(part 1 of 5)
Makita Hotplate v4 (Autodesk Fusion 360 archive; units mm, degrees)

design "Makita Hotplate" references "Hotplate Toolchanger", "Makita RT0700 v10"
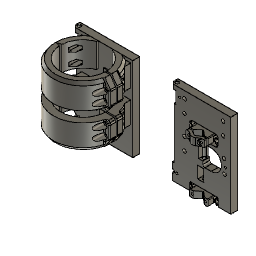
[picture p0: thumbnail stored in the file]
external_derived "ExternalDerived1"
split "Split1" bodies "Hotplate Cam Template (1)"
external_derived "ExternalDerived2"
move "Move1"
move "Move2"
move "Move3"
move "Move4"
work_plane "WorkPlane1"
work_plane "WorkPlane2" AlongDistance -29
sketch "Sketch1" plane through (7.3531, -5.0045, 68.3543) normal (0, 0, -1) x axis (1, 0, 0)
  line L1 (0, 1.1219) -> (0, 0)
  line L2 (-2.2027, 1.1219) -> (0, 1.1219)
  curve K1 (-2.2027, 1.1219) -> (-1.8409, 0.1808)
  line L3 (0, 1.1219) -> (0, 0)
  line L4 (4.5, 1.1219) -> (4.5, 0)
  line L5 (0.8469, -0.0045) -> (-5.1531, -0.0045)
  line L6 (0.8469, -0.0045) -> (3.6753, -0.0045)
  line L7 (12.6469, -0.0045) -> (3.6753, -0.0045)
  line L8 (12.6469, -0.0045) -> (27.1469, -0.0045)
  line L9 (3.6753, -0.0045) -> (12.6469, -0.0045)
  line L10 (3.6753, -0.0045) -> (0.8469, -0.0045)
  line L11 (-5.1531, -0.0045) -> (0.8469, -0.0045)
  line L12 (31.4969, -0.0045) -> (34.7969, -0.0045)
  line L13 (-34.0031, -0.0045) -> (-30.7031, -0.0045)
  line L14 (-38.0031, -0.0045) -> (-34.7031, -0.0045)
  line L15 (1.8969, -0.0045) -> (-6.6031, -0.0045)
  line L16 (-6.6031, -0.0045) -> (1.8969, -0.0045)
  line L17 (37.6469, -0.0045) -> (-42.8531, -0.0045)
  line L18 (-41.7031, -0.0045) -> (37.6469, -0.0045)
  line L19 (-37.7031, -0.0045) -> (-41.7031, -0.0045)
  line L20 (-35.3531, -0.0045) -> (-37.7031, -0.0045)
  line L21 (-34.8531, -0.0045) -> (-35.3531, -0.0045)
  line L22 (-35.3531, -0.0045) -> (-34.8531, -0.0045)
  line L23 (-42.8531, -0.0045) -> (-35.3531, -0.0045)
  line L24 (-38.9531, -0.0045) -> (-42.8531, -0.0045)
  line L25 (-42.8531, -0.0045) -> (-38.9531, -0.0045)
  line L26 (4.5, 1.1219) -> (0, 1.1219)
  line L27 (0, 0) -> (0, 1.1219)
  line L28 (4.5, 1.1219) -> (0, 1.1219)
  line L29 (4.5, 0) -> (4.5, 1.1219)
  line L30 (0, 0) -> (4.5, 0)
  line L31 (0, 1.1219) -> (0, 0)
  arc A1 centre (2.25, 32.3719) radius 32.45 clockwise from (0, 0) to (-1.8409, 0.1808)
  point P5 (0, 1.1219)
  point P31 (0, 1.1219)
  point P10 (4.5, 1.1219)
  point P32 (4.5, 1.1219)
  point P8 (0, 1.1219)
  point P33 (0, 1.1219)
  point P3 (0, 0)
  point P34 (0, 0)
  point P9 (4.5, 0)
  point P36 (4.5, 0)
  coincident P5 P31
  coincident P10 P32
  coincident P8 P33
  coincident P3 P34
  horizontal L28
  vertical L29
  horizontal L30
  vertical L31
  coincident P9 P36
extrude "Extrude1" new body sketch "Sketch1" profile of L1 L3 L4 L26 L27 L28 L29 L30 L31 to an object
extrude "Extrude2" add of existing geometry blind 5.5
sketch "Sketch2" plane through (0, -5, 0) normal (0, -1, 0) x axis (1, 0, 0)
  line L1 (8.2, 63) -> (2.2, 63)
  line L2 (8.2, 65.1716) -> (8.2, 63)
  curve K1 (8.2, 65.1716) -> (11.0284, 68)
  line L3 (20, 68) -> (11.0284, 68)
  line L4 (11.0284, 39) -> (20, 39)
  curve K2 (11.0284, 39) -> (8.2, 41.8284)
  line L5 (8.2, 46) -> (8.2, 41.8284)
  line L6 (2.2, 46) -> (8.2, 46)
  line L7 (2.2, 63) -> (2.2, 46)
  line L8 (9.25, 37) -> (0.75, 37)
  line L9 (9.25, 20) -> (9.25, 37)
  line L10 (0.75, 20) -> (9.25, 20)
  line L11 (0.75, 37) -> (0.75, 20)
  line L12 (-35.5, 0) -> (-35.5, 8.6225)
  line L13 (45, 0) -> (-35.5, 0)
  line L14 (45, 120) -> (45, 0)
  line L15 (-34.35, 120) -> (45, 120)
  line L16 (-34.35, 114) -> (-34.35, 120)
  line L17 (-30.35, 114) -> (-34.35, 114)
  line L18 (-30.35, 96.75) -> (-30.35, 114)
  line L19 (-28, 96.75) -> (-30.35, 96.75)
  line L20 (-28, 73.95) -> (-28, 96.75)
  line L21 (-27.5, 73.95) -> (-28, 73.95)
  line L22 (-27.5, 46.05) -> (-27.5, 73.95)
  line L23 (-28, 46.05) -> (-27.5, 46.05)
  line L24 (-28, 23.25) -> (-28, 46.05)
  line L25 (-35.5, 23.25) -> (-28, 23.25)
  line L26 (-35.5, 15.3775) -> (-35.5, 23.25)
  line L27 (-31.6, 12) -> (-35.5, 15.3775)
  line L28 (-35.5, 8.6225) -> (-31.6, 12)
  arc A1 centre (20, 53.5) radius 14.5 clockwise from (20, 68) to (20, 39)
  circle C1 centre (40.5, 54) radius 1.65
  circle C2 centre (-25, 108) radius 1.65
  circle C3 centre (-29, 12) radius 1.65
sketch "Sketch3" plane through (0, -6.1264, 0) normal (0, -1, 0) x axis (1, 0, 0)
  line L1 (7.3531, 91.3543) -> (11.8531, 91.3543)
  line L2 (7.3531, 62.8543) -> (7.3531, 91.3543)
  line L3 (11.8531, 62.8543) -> (7.3531, 62.8543)
  line L4 (11.8531, 91.3543) -> (11.8531, 62.8543)
  line L5 (8.2, 63) -> (2.2, 63)
  line L6 (8.2, 65.1716) -> (8.2, 63)
  curve K1 (8.2, 65.1716) -> (11.0284, 68)
  line L7 (20, 68) -> (11.0284, 68)
  line L8 (11.0284, 39) -> (20, 39)
  curve K2 (11.0284, 39) -> (8.2, 41.8284)
  line L9 (8.2, 46) -> (8.2, 41.8284)
  line L10 (2.2, 46) -> (8.2, 46)
  line L11 (2.2, 63) -> (2.2, 46)
  line L12 (9.25, 37) -> (0.75, 37)
  line L13 (9.25, 20) -> (9.25, 37)
  line L14 (0.75, 20) -> (9.25, 20)
  line L15 (0.75, 37) -> (0.75, 20)
  line L16 (-35.5, 0) -> (-35.5, 8.6225)
  line L17 (45, 0) -> (-35.5, 0)
  line L18 (45, 120) -> (45, 0)
  line L19 (-34.35, 120) -> (45, 120)
  line L20 (-34.35, 114) -> (-34.35, 120)
  line L21 (-30.35, 114) -> (-34.35, 114)
  line L22 (-30.35, 96.75) -> (-30.35, 114)
  line L23 (-28, 96.75) -> (-30.35, 96.75)
  line L24 (-28, 73.95) -> (-28, 96.75)
  line L25 (-27.5, 73.95) -> (-28, 73.95)
  line L26 (-27.5, 46.05) -> (-27.5, 73.95)
  line L27 (-28, 46.05) -> (-27.5, 46.05)
  line L28 (-28, 23.25) -> (-28, 46.05)
  line L29 (-35.5, 23.25) -> (-28, 23.25)
  line L30 (-35.5, 15.3775) -> (-35.5, 23.25)
  line L31 (-31.6, 12) -> (-35.5, 15.3775)
  line L32 (-35.5, 8.6225) -> (-31.6, 12)
  arc A1 centre (20, 53.5) radius 14.5 clockwise from (20, 68) to (20, 39)
  circle C1 centre (40.5, 54) radius 1.65
  circle C2 centre (-25, 108) radius 1.65
  circle C3 centre (-29, 12) radius 1.65
extrude "Extrude3" new body blind 6 second side blind 3
split "Split2"
combine "Combine1" bodies "Hotplate Cam Template"
combine "Combine2"
extrude "Extrude4" add of existing geometry blind -5
sketch "Sketch4" plane through (-28, 0, 0) normal (-1, 0, 0) x axis (0, -1, 0)
  line L1 (5, 96.75) -> (5, 73.95)
  line L2 (-0.7, 96.75) -> (5, 96.75)
  line L3 (-0.7, 73.95) -> (-0.7, 96.75)
  line L4 (5, 73.95) -> (-0.7, 73.95)
  line L5 (-5, 98.4571) -> (-5, 97.25)
  line L6 (-5, 114) -> (-5, 98.4571)
  line L7 (-5, 120) -> (-5, 114)
  line L8 (-5, 0) -> (-5, 120)
  line L9 (-5, 22.25) -> (-5, 0)
  line L10 (-5, 22.75) -> (-5, 22.25)
  line L11 (-5, 97.25) -> (-5, 22.75)
  line L12 (-5, 37) -> (-5, 20)
  line L13 (-5, 20) -> (-5, 37)
  line L14 (-5, 10.35) -> (-5, 13.65)
  line L15 (-5, 106.35) -> (-5, 109.65)
  line L16 (-5, 52.35) -> (-5, 55.65)
  line L17 (-5, 63) -> (-5, 65.1716)
  line L18 (-5, 46) -> (-5, 63)
  line L19 (-5, 41.8284) -> (-5, 46)
  line L20 (-5, 41.8284) -> (-5, 39)
  line L21 (-5, 39) -> (-5, 68)
  line L22 (-5, 68) -> (-5, 65.1716)
  line L23 (-5, 96.75) -> (5, 96.75)
  line L24 (-5, 22.75) -> (-5, 96.75)
  line L25 (5, 22.75) -> (-5, 22.75)
  line L26 (5, 96.75) -> (5, 22.75)
  circle C1 centre (3, 92.5) radius 1.75
  circle C2 centre (3, 76.45) radius 0.85
  point P15 (-5, 22.75)
  point P32 (-5, 22.75)
  point P8 (5, 96.75)
  point P30 (5, 96.75)
  horizontal L23
  vertical L24
  horizontal L25
  vertical L26
  coincident P15 P32
  coincident P8 P30
extrude "Extrude5" add sketch "Sketch4" profile of C1 C2 L1 L2 L3 L4 L8 L11 L12 L13 L16 L17 L18 L19 L20 L21 L22 L23 L24 L25 L26 along normal blind 5 and against normal blind 10
sketch "Sketch5" plane through (0, 0, 120) normal (0, 0, 1) x axis (-1, 0, 0)
  line L1 (34.35, 5) -> (37.35, 2)
  line L2 (-45, 5) -> (34.35, 5)
  line L3 (-45, -5) -> (-45, 5)
  line L4 (37.35, -5) -> (-45, -5)
  line L5 (37.35, 2) -> (37.35, -5)
  line L6 (-11.8531, 5) -> (-7.3531, 5)
  line L7 (-20, 5) -> (-11.8531, 5)
  line L8 (-34.5, 5) -> (-20, 5)
  line L9 (-11.0284, 5) -> (-20, 5)
  line L10 (-11.0284, 5) -> (-8.2, 5)
  line L11 (-2.2, 5) -> (-8.2, 5)
  line L12 (-7.3531, 5) -> (-2.2, 5)
  line L13 (-42.15, 5) -> (-38.85, 5)
  line L14 (23.35, 5) -> (26.65, 5)
  line L15 (27.35, 5) -> (30.65, 5)
  line L16 (-9.25, 5) -> (-0.75, 5)
  line L17 (-0.75, 5) -> (-9.25, 5)
  line L18 (33, 5) -> (30.35, 5)
  line L19 (35.5, 5) -> (33, 5)
  line L20 (31.6, 5) -> (35.5, 5)
  line L21 (35.5, 5) -> (31.6, 5)
  line L22 (-45, 5) -> (35.5, 5)
  line L23 (34.35, 5) -> (-45, 5)
  line L24 (30.35, 5) -> (34.35, 5)
  circle C1 centre (33.35, 0) radius 2.625
  arc A1 centre (-9.6031, 37.3764) radius 32.45 clockwise from (22.7653, 39.6764) to (22.7653, 35.0764)
  arc A2 centre (-9.6031, 37.3764) radius 32.45 clockwise from (22.7653, 39.6764) to (22.8469, 37.3764)
  arc A3 centre (-9.6031, 37.3764) radius 32.45 clockwise from (-13.694, 5.1853) to (22.8469, 37.3764)
  arc A4 centre (-9.6031, 37.3764) radius 32.45 clockwise from (-11.8531, 5.0045) to (-13.694, 5.1853)
  arc A5 centre (-9.6031, 37.3764) radius 32.45 clockwise from (-7.3531, 5.0045) to (-11.8531, 5.0045)
  arc A6 centre (-9.6031, 37.3764) radius 32.45 clockwise from (-5.5122, 5.1853) to (-7.3531, 5.0045)
  arc A7 centre (-9.6031, 37.3764) radius 32.45 clockwise from (22.8469, 37.3764) to (-5.5122, 5.1853)
  arc A8 centre (-9.6031, 37.3764) radius 32.45 clockwise from (22.8469, 37.3764) to (22.7653, 35.0764)
  arc A9 centre (-9.6031, 37.3764) radius 32.45 clockwise from (22.7653, 39.6764) to (22.7653, 35.0764)
  arc A10 centre (-9.6031, 37.3764) radius 32.45 clockwise from (22.7653, 39.6764) to (22.7653, 35.0764)
  arc A11 centre (-9.6031, 37.3764) radius 32.45 clockwise from (22.7653, 39.6764) to (22.7653, 35.0764)
  arc A12 centre (-9.6031, 37.3764) radius 32.45 clockwise from (22.7653, 39.6764) to (22.7653, 35.0764)
  arc A13 centre (-9.6031, 37.3764) radius 32.45 clockwise from (22.7653, 39.6764) to (22.7653, 35.0764)
  arc A14 centre (-9.6031, 37.3764) radius 32.45 clockwise from (22.7653, 39.6764) to (22.7653, 35.0764)
  arc A15 centre (-9.6031, 37.3764) radius 32.45 clockwise from (22.7653, 39.6764) to (22.7653, 35.0764)
  arc A16 centre (-9.6031, 37.3764) radius 32.45 clockwise from (22.7653, 39.6764) to (22.7653, 35.0764)
  arc A17 centre (-9.6031, 37.3764) radius 32.45 clockwise from (22.7653, 39.6764) to (22.7653, 35.0764)
  arc A18 centre (-9.6031, 37.3764) radius 32.45 clockwise from (22.7653, 39.6764) to (22.7653, 35.0764)
  arc A19 centre (-9.6031, 37.3764) radius 32.45 clockwise from (22.7653, 39.6764) to (22.7653, 35.0764)
  arc A20 centre (-9.6031, 37.3764) radius 32.45 clockwise from (22.7653, 39.6764) to (22.7653, 35.0764)
  arc A21 centre (-9.6031, 37.3764) radius 32.45 clockwise from (22.7653, 39.6764) to (22.7653, 35.0764)
  arc A22 centre (-9.6031, 37.3764) radius 32.45 clockwise from (22.7653, 39.6764) to (22.7653, 35.0764)
  arc A23 centre (-9.6031, 37.3764) radius 32.45 clockwise from (22.7653, 39.6764) to (22.7653, 35.0764)
  arc A24 centre (-9.6031, 37.3764) radius 32.45 clockwise from (22.7653, 39.6764) to (22.7653, 35.0764)
  arc A25 centre (-9.6031, 37.3764) radius 32.45 clockwise from (22.7653, 39.6764) to (22.7653, 35.0764)
  arc A26 centre (-9.6031, 37.3764) radius 32.45 clockwise from (22.7653, 39.6764) to (22.7653, 35.0764)
  arc A27 centre (-9.6031, 37.3764) radius 32.45 clockwise from (22.7653, 39.6764) to (22.7653, 35.0764)
  arc A28 centre (-9.6031, 37.3764) radius 32.45 clockwise from (22.7653, 39.6764) to (22.7653, 35.0764)
  arc A29 centre (-9.6031, 37.3764) radius 32.45 clockwise from (22.7653, 39.6764) to (22.7653, 35.0764)
  arc A30 centre (-9.6031, 37.3764) radius 32.45 clockwise from (22.7653, 39.6764) to (22.7653, 35.0764)
  arc A31 centre (-9.6031, 37.3764) radius 32.45 clockwise from (22.7653, 39.6764) to (22.7653, 35.0764)
  arc A32 centre (-9.6031, 37.3764) radius 32.45 clockwise from (22.7653, 39.6764) to (22.7653, 35.0764)
  arc A33 centre (-9.6031, 37.3764) radius 32.45 clockwise from (22.7653, 39.6764) to (22.7653, 35.0764)
  arc A34 centre (-9.6031, 37.3764) radius 32.45 clockwise from (22.7653, 39.6764) to (22.7653, 35.0764)
  arc A35 centre (-9.6031, 37.3764) radius 32.45 clockwise from (22.7653, 39.6764) to (22.7653, 35.0764)
  arc A36 centre (-9.6031, 37.3764) radius 32.45 clockwise from (22.7653, 39.6764) to (22.7653, 35.0764)
  arc A37 centre (-9.6031, 37.3764) radius 32.45 clockwise from (22.7653, 39.6764) to (22.7653, 35.0764)
  arc A38 centre (-9.6031, 37.3764) radius 32.45 clockwise from (22.7653, 39.6764) to (22.7653, 35.0764)
  arc A39 centre (-9.6031, 37.3764) radius 32.45 clockwise from (22.7653, 39.6764) to (22.7653, 35.0764)
  arc A40 centre (-9.6031, 37.3764) radius 32.45 clockwise from (22.7653, 39.6764) to (22.7653, 35.0764)
  arc A41 centre (-9.6031, 37.3764) radius 32.45 clockwise from (22.7653, 39.6764) to (22.7653, 35.0764)
  arc A42 centre (-9.6031, 37.3764) radius 32.45 clockwise from (22.7653, 39.6764) to (22.7653, 35.0764)
  arc A43 centre (-9.6031, 37.3764) radius 32.45 clockwise from (22.7653, 39.6764) to (22.7653, 35.0764)
  arc A44 centre (-9.6031, 37.3764) radius 32.45 clockwise from (22.7653, 39.6764) to (22.7653, 35.0764)
  arc A45 centre (-9.6031, 37.3764) radius 32.45 clockwise from (22.7653, 39.6764) to (22.7653, 35.0764)
  arc A46 centre (-9.6031, 37.3764) radius 32.45 clockwise from (22.7653, 39.6764) to (22.7653, 35.0764)
  arc A47 centre (-9.6031, 37.3764) radius 32.45 clockwise from (22.7653, 39.6764) to (22.7653, 35.0764)
  arc A48 centre (-9.6031, 37.3764) radius 32.45 clockwise from (22.7653, 39.6764) to (22.7653, 35.0764)
  arc A49 centre (-9.6031, 37.3764) radius 32.45 clockwise from (22.7653, 39.6764) to (22.7653, 35.0764)
  arc A50 centre (-9.6031, 37.3764) radius 32.45 clockwise from (22.7653, 39.6764) to (22.7653, 35.0764)
  arc A51 centre (-9.6031, 37.3764) radius 32.45 clockwise from (22.7653, 39.6764) to (22.7653, 35.0764)
  arc A52 centre (-9.6031, 37.3764) radius 32.45 clockwise from (22.7653, 39.6764) to (22.7653, 35.0764)
  circle C2 centre (-9.6031, 37.3764) radius 32.45
  arc A53 centre (-9.6031, 37.3764) radius 32.45 clockwise from (22.7653, 39.6764) to (22.7653, 35.0764)
  arc A54 centre (-9.6031, 37.3764) radius 32.45 clockwise from (22.7653, 39.6764) to (22.7653, 35.0764)
  circle C3 centre (-9.6031, 37.3764) radius 42.45
  dimension "d16" = 10
extrude "Extrude6" new body sketch "Sketch5" profile of L2 A1 A2 A3 A4 A5 A6 A7 A8 A9 A10 A11 A12 A13 A14 A15 A16 A17 A18 A19 A20 A21 A22 A23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 against normal blind 35
copy_paste_bodies "CopyPasteBodies1"
move "Move5"
extrude "Extrude7" cut sketch "Sketch2" profile of L1 L2 K1 L3 A1 L4 K2 L5 L6 L7 along normal blind 15
chamfer "Chamfer1" distance 3 Rotate Angle 55 bodies "Body1 (1)"
combine "Combine3"
sketch "Sketch6" plane through (45, 0, 0) normal (1, 0, 0) x axis (0, 1, 0)
  line L1 (5, 120) -> (5, 0)
  line L2 (-5, 120) -> (5, 120)
  line L3 (-5, 0) -> (-5, 120)
  line L4 (5, 0) -> (-5, 0)
  line L5 (-79.8264, 115.7156) -> (-5, 115.7156)
  line L6 (-5, 85) -> (-79.8264, 85)
  line L7 (-79.8264, 70) -> (-5, 70)
  line L8 (-5, 39.2844) -> (-79.8264, 39.2844)
  line L9 (-14.1517, 115.7156) -> (-5, 115.7156)
  line L10 (-14.1517, 85) -> (-14.1517, 115.7156)
  line L11 (-5, 85) -> (-14.1517, 85)
  line L12 (-5, 115.7156) -> (-5, 85)
  line L13 (-14.4254, 70) -> (-5, 70)
  line L14 (-14.4254, 39.2844) -> (-14.4254, 70)
  line L15 (-5, 39.2844) -> (-14.4254, 39.2844)
  line L16 (-5, 70) -> (-5, 39.2844)
  point P16 (-14.1517, 85)
  point P6 (-5, 115.7156)
  point P14 (-5, 115.7156)
  point P20 (-14.4254, 39.2844)
  point P10 (-5, 70)
  point P18 (-5, 70)
  horizontal L9
  vertical L10
  horizontal L11
  vertical L12
  coincident L6 P16
  coincident P6 P14
  horizontal L13
  vertical L14
  horizontal L15
  vertical L16
  coincident L8 P20
  coincident P10 P18
extrude "Extrude8" new body sketch "Sketch6" profile of L3 L5 L6 L7 L8 L9 L10 L11 L12 L13 L14 L15 L16 against normal blind 70
split "Split3"
combine "Combine4"
split "Split4"
sketch "Sketch7" plane through (0, -5, 0) normal (0, 1, 0) x axis (-1, 0, 0)
  line L1 (-0.75, 37) -> (-0.75, 35)
  line L2 (-7.4192, 37) -> (-0.75, 37)
  line L3 (-7.4192, 35) -> (-7.4192, 37)
  line L4 (-0.75, 35) -> (-7.4192, 35)
extrude "Extrude9" cut sketch "Sketch7" against normal blind 12
sketch "Sketch8" plane through (0, 0, 70) normal (0, 0, 1) x axis (-1, 0, 0)
  line L1 (-11.8531, 5) -> (-37.058, 5)
  line L2 (-11.8531, 5.0045) -> (-11.8531, 5)
  line L3 (-7.3531, 5) -> (-7.3531, 5.0045)
  line L4 (25, 5) -> (-7.3531, 5)
  line L5 (25, 12.7873) -> (25, 5)
  line L6 (-45, 5) -> (-45, -5)
  line L7 (-45, 13.9443) -> (-45, 5)
  line L8 (-45, 5) -> (-45, 13.9443)
  line L9 (-45, -5) -> (-45, 5)
  line L10 (-45, 5) -> (-37.058, 5)
  arc A1 centre (-9.6031, 37.3764) radius 42.45 clockwise from (-37.058, 5) to (25, 12.7873)
  arc A2 centre (-9.6031, 37.3764) radius 32.45 clockwise from (-11.8531, 5.0045) to (-7.3531, 5.0045)
  arc A3 centre (-9.6031, 37.3764) radius 42.45 clockwise from (-37.058, 5) to (25, 12.7873)
  point P14 (-37.058, 5)
  point P16 (-37.058, 5)
  point P11 (-45, 5)
  point P17 (-45, 5)
  coincident P14 P16
  coincident P11 P17
extrude "Extrude10" add sketch "Sketch8" profile of A1 L7 L8 A3 L10 against normal blind 30.716
sketch "Sketch9" plane through (0, 0, 120) normal (0, 0, 1) x axis (-1, 0, 0)
  line L1 (-45, 5) -> (-32.1435, 5)
  line L2 (-45, -5) -> (-45, 5)
  line L3 (37.35, -5) -> (-45, -5)
  line L4 (37.35, 2) -> (37.35, -5)
  line L5 (34.35, 5) -> (37.35, 2)
  line L6 (12.9373, 5) -> (34.35, 5)
  line L7 (-11.787, 5) -> (-7.4192, 5)
  arc A1 centre (-9.6031, 37.3764) radius 39.45 clockwise from (-32.1435, 5) to (12.9373, 5)
  circle C1 centre (33.35, 0) radius 2.625
  arc A2 centre (-9.6031, 37.3764) radius 32.45 clockwise from (-11.787, 5) to (-7.4192, 5)
  arc A3 centre (-9.6031, 37.3764) radius 32.45 clockwise from (-11.787, 5) to (-7.4192, 5)
sketch "Sketch10" plane through (0, 0, 120) normal (0, 0, 1) x axis (-1, 0, 0)
  line L1 (-45, 5) -> (-32.1435, 5)
  line L2 (-45, -5) -> (-45, 5)
  line L3 (37.35, -5) -> (-45, -5)
  line L4 (37.35, 2) -> (37.35, -5)
  line L5 (34.35, 5) -> (37.35, 2)
  line L6 (12.9373, 5) -> (34.35, 5)
  line L7 (-11.787, 5) -> (-7.4192, 5)
  line L8 (-68.9773, 5) -> (34.35, 5)
  line L9 (-68.9773, 90.7472) -> (-68.9773, 5)
  line L10 (34.35, 90.7472) -> (-68.9773, 90.7472)
  line L11 (34.35, 5) -> (34.35, 90.7472)
  arc A1 centre (-9.6031, 37.3764) radius 39.45 clockwise from (-32.1435, 5) to (12.9373, 5)
  circle C1 centre (33.35, 0) radius 2.625
  arc A2 centre (-9.6031, 37.3764) radius 32.45 clockwise from (-11.787, 5) to (-7.4192, 5)
  point P9 (34.35, 5)
  point P15 (34.35, 5)
  horizontal L8
  vertical L9
  horizontal L10
  vertical L11
  coincident P9 P15
extrude "Extrude11" new body sketch "Sketch10" profile of A1 L1 L6 L7 A2 L8 L9 L10 L11 against normal blind 145
split "Split5"
sketch "Sketch11" plane through (0, -5, 0) normal (0, -1, 0) x axis (1, 0, 0)
  line L1 (11.0284, 39) -> (20, 39)
  curve K1 (11.0284, 39) -> (8.2, 41.8284)
  line L2 (8.2, 46) -> (8.2, 41.8284)
  line L3 (2.2, 46) -> (8.2, 46)
  line L4 (2.2, 63) -> (2.2, 46)
  line L5 (8.2, 63) -> (2.2, 63)
  line L6 (8.2, 65.1716) -> (8.2, 63)
  curve K2 (8.2, 65.1716) -> (11.0284, 68)
  line L7 (20, 68) -> (11.0284, 68)
  line L8 (9.25, 37) -> (0.75, 37)
  line L9 (9.25, 20) -> (9.25, 37)
  line L10 (0.75, 20) -> (9.25, 20)
  line L11 (0.75, 37) -> (0.75, 20)
  line L12 (-35.5, 8.6225) -> (-31.6, 12)
  line L13 (-35.5, 0) -> (-35.5, 8.6225)
  line L14 (45, 0) -> (-35.5, 0)
  line L15 (45, 120) -> (45, 0)
  line L16 (-34.35, 120) -> (45, 120)
  line L17 (-34.35, 114) -> (-34.35, 120)
  line L18 (-30.35, 114) -> (-34.35, 114)
  line L19 (-30.35, 96.75) -> (-30.35, 114)
  line L20 (-33, 96.75) -> (-30.35, 96.75)
  line L21 (-33, 23.25) -> (-33, 96.75)
  line L22 (-35.5, 23.25) -> (-33, 23.25)
  line L23 (-35.5, 15.3775) -> (-35.5, 23.25)
  line L24 (-31.6, 12) -> (-35.5, 15.3775)
  line L25 (11.8531, 68) -> (11.0284, 68)
  line L26 (11.8531, 91.3543) -> (11.8531, 68)
  line L27 (7.3531, 91.3543) -> (11.8531, 91.3543)
  line L28 (7.3531, 63) -> (7.3531, 91.3543)
  line L29 (8.2, 63) -> (7.3531, 63)
  line L30 (8.2, 65.1716) -> (8.2, 63)
  curve K3 (11.0284, 68) -> (8.2, 65.1716)
  arc A1 centre (20, 53.5) radius 14.5 clockwise from (20, 68) to (20, 39)
  circle C1 centre (-25, 108) radius 1.65
  circle C2 centre (40.5, 54) radius 1.65
  circle C3 centre (-29, 12) radius 1.65
extrude "Extrude12" add sketch "Sketch11" profile of L5 L6 K2 L7 L25 L26 L27 L28 L29 L30 K3 along normal blind 1.122
extrude "Extrude13" cut of existing geometry blind -39
sketch "Sketch12" plane through (0, 0, 120) normal (0, 0, 1) x axis (-1, 0, 0)
  line L1 (-11.787, 5) -> (-32.1435, 5)
  line L2 (12.9373, 5) -> (-7.4192, 5)
  line L3 (29.1901, 37.3764) -> (-9.6031, 37.3764)
  line L4 (28.4052, 37.1373) -> (22.7882, 35.4258)
  line L5 (28.4052, 37.6156) -> (22.7882, 39.3271)
  arc A1 centre (-9.6031, 37.3764) radius 32.45 clockwise from (-11.787, 5) to (-7.4192, 5)
  arc A2 centre (-9.6031, 37.3764) radius 39.45 clockwise from (-32.1435, 5) to (12.9373, 5)
  arc A3 centre (-9.6031, 37.3764) radius 32.45 clockwise from (-11.787, 5) to (-7.4192, 5)
  arc A4 centre (28.3324, 37.3764) radius 0.25 clockwise from (28.4052, 37.6156) to (28.4052, 37.1373)
  point P9 (-9.6031, 37.3764)
  point P10 (-9.6031, 37.3764)
  point P12 (22.7882, 35.4258)
  point P13 (22.7882, 39.3271)
  point P11 (29.1901, 37.3764)
  coincident P9 P10
  horizontal L3
  coincident A3 P12
  symmetric L3 P12 P13
  coincident P11 L4
  tangent L4 A4
  tangent L5 A4
  dimension "d35" radius A4 = 0.25
extrude "Extrude14" cut sketch "Sketch12" profile of A1 A3 L3 L4 L5 A4 against normal blind 110
sketch "Sketch13" plane through (0, 0, 120) normal (0, 0, 1) x axis (-1, 0, 0)
  line L1 (28.4052, 37.6156) -> (22.7882, 39.3271)
  line L2 (22.7882, 35.4258) -> (28.4052, 37.1373)
  line L3 (12.9373, 5) -> (-7.4192, 5)
  line L4 (-11.787, 5) -> (-32.1435, 5)
  line L5 (-60.2288, 37.3764) -> (-9.6031, 37.3764)
  line L6 (-53.7484, 37.3764) -> (-39.6632, 37.3764)
  line L7 (-53.7484, 36.8764) -> (-53.7484, 37.3764)
  line L8 (-39.6632, 36.8764) -> (-53.7484, 36.8764)
  line L9 (-39.6632, 37.3764) -> (-39.6632, 36.8764)
  line L10 (-39.6632, 37.3764) -> (-39.6632, 37.8764)
  line L11 (-39.6632, 37.8764) -> (-53.7484, 37.8764)
  line L12 (-53.7484, 37.8764) -> (-53.7484, 37.3764)
  arc A1 centre (28.3324, 37.3764) radius 0.25 clockwise from (28.4052, 37.6156) to (28.4052, 37.1373)
  arc A2 centre (-9.6031, 37.3764) radius 32.45 clockwise from (22.7882, 35.4258) to (-7.4192, 5)
  arc A3 centre (-9.6031, 37.3764) radius 39.45 clockwise from (-32.1435, 5) to (12.9373, 5)
  arc A4 centre (-9.6031, 37.3764) radius 32.45 clockwise from (-11.787, 5) to (22.7882, 39.3271)
  arc A5 centre (-9.6031, 37.3764) radius 32.45 clockwise from (-11.787, 5) to (22.7882, 39.3271)
  point P14 (-9.6031, 37.3764)
  point P15 (-9.6031, 37.3764)
  point P17 (-39.6632, 37.3764)
  point P22 (-39.6632, 37.3764)
  point P18 (-53.7484, 37.3764)
  point P24 (-53.7484, 37.3764)
  point P19 (-53.7484, 36.8764)
  point P23 (-53.7484, 37.8764)
  point P20 (-39.6632, 36.8764)
  point P21 (-39.6632, 37.8764)
  coincident P14 P15
  horizontal L5
  horizontal L6
  vertical L7
  horizontal L8
  vertical L9
  coincident L5 P17
  symmetric L5 P17 P22
  symmetric L5 P18 P24
  symmetric L5 P19 P23
  symmetric L5 P20 P21
  dimension "d38" distance P17 P20 = 0.5
extrude "Extrude15" cut sketch "Sketch13" profile of A3 A4 A5 L5 L6 L7 L8 L9 L10 L11 L12 against normal blind 170
sketch "Sketch14" plane through (0, 0, 120) normal (0, 0, 1) x axis (-1, 0, 0)
  line L1 (-42.0493, 37.8764) -> (-49.05, 37.8764)
  line L2 (28.4052, 37.6156) -> (22.7882, 39.3271)
  line L3 (22.7882, 35.4258) -> (28.4052, 37.1373)
  line L4 (12.9373, 5) -> (-7.4192, 5)
  line L5 (1.7227, 8.5554) -> (1.7227, 5)
  line L6 (-20.0313, 8.5554) -> (1.7227, 8.5554)
  line L7 (-20.0313, 2.3632) -> (-20.0313, 8.5554)
  line L8 (1.7227, 2.3632) -> (-20.0313, 2.3632)
  line L9 (1.7227, 5) -> (1.7227, 2.3632)
  arc A1 centre (-9.6031, 37.3764) radius 32.45 clockwise from (-42.0493, 37.8764) to (22.7882, 39.3271)
  arc A2 centre (28.3324, 37.3764) radius 0.25 clockwise from (28.4052, 37.6156) to (28.4052, 37.1373)
  arc A3 centre (-9.6031, 37.3764) radius 32.45 clockwise from (22.7882, 35.4258) to (-7.4192, 5)
  arc A4 centre (-9.6031, 37.3764) radius 39.45 clockwise from (-49.05, 37.8764) to (12.9373, 5)
  point P12 (1.7227, 5)
  coincident L4 P12
  perpendicular L4 L5
  perpendicular L5 L6
  perpendicular L6 L7
  perpendicular L5 L8
  perpendicular L4 L9
extrude "Extrude16" cut sketch "Sketch14" profile of A3 L4 L5 L6 L7 L8 L9 against normal blind 95
sketch "Sketch15" plane through (0, 0, 120) normal (0, 0, 1) x axis (-1, 0, 0)
  line L1 (-45, 5) -> (34.35, 5)
  line L2 (-45, -5) -> (-45, 5)
  line L3 (37.35, -5) -> (-45, -5)
  line L4 (37.35, 2) -> (37.35, -5)
  line L5 (34.35, 5) -> (37.35, 2)
  line L6 (37.35, -5) -> (-45, -5)
  line L7 (-52.6729, -5) -> (29.2933, -5)
  line L8 (-52.6729, 16) -> (-52.6729, -5)
  line L9 (29.2933, 16) -> (-52.6729, 16)
  line L10 (29.2933, -5) -> (29.2933, 16)
  line L11 (19.8506, -16.4747) -> (19.8506, 16)
  line L12 (15.8506, 16) -> (19.8506, 16)
  line L13 (15.8506, -32.4525) -> (15.8506, 16)
  line L14 (19.8506, -32.4525) -> (15.8506, -32.4525)
  line L15 (19.8506, 16) -> (19.8506, -32.4525)
  circle C1 centre (33.35, 0) radius 2.625
  point P10 (29.2933, -5)
  point P14 (19.8506, 16)
  point P13 (29.2933, 16)
  point P16 (15.8506, 16)
  horizontal L7
  vertical L8
  horizontal L9
  vertical L10
  coincident L3 P10
  coincident L9 P14
  perpendicular L9 L11
  horizontal L12
  vertical L13
  horizontal L14
  vertical L15
  dimension "d43" distance P10 P13 = 21
  dimension "d44" distance P14 P16 = 4
sketch "Sketch16" plane through (0, 0, 120) normal (0, 0, 1) x axis (-1, 0, 0)
  line L1 (1.7227, 5) -> (1.7227, 6.9671)
  line L2 (12.9373, 5) -> (1.7227, 5)
  line L3 (-42.0493, 37.8764) -> (-49.05, 37.8764)
  line L4 (28.4052, 37.6156) -> (22.7882, 39.3271)
  line L5 (22.7882, 35.4258) -> (28.4052, 37.1373)
  line L6 (-9.6031, 46.5679) -> (-9.6031, 37.3764)
  arc A1 centre (-9.6031, 37.3764) radius 39.45 clockwise from (-49.05, 37.8764) to (12.9373, 5)
  arc A2 centre (-9.6031, 37.3764) radius 32.45 clockwise from (-42.0493, 37.8764) to (22.7882, 39.3271)
  arc A3 centre (28.3324, 37.3764) radius 0.25 clockwise from (28.4052, 37.6156) to (28.4052, 37.1373)
  arc A4 centre (-9.6031, 37.3764) radius 32.45 clockwise from (22.7882, 35.4258) to (1.7227, 6.9671)
  arc A5 centre (-9.6031, 37.3764) radius 32.45 clockwise from (-42.0493, 37.8764) to (22.7882, 39.3271)
  point P15 (-9.6031, 37.3764)
  point P16 (-9.6031, 37.3764)
  coincident P15 P16
  vertical L6
sketch "Sketch17" plane through (0, 5, 0) normal (0, 1, 0) x axis (-1, 0, 0)
  line L1 (27, 97.25) -> (27, 96.75)
  line L2 (33.7929, 97.25) -> (27, 97.25)
  line L3 (35, 98.4571) -> (33.7929, 97.25)
  line L4 (35, 114) -> (35, 98.4571)
  line L5 (37.35, 114) -> (35, 114)
  line L6 (37.35, 120) -> (37.35, 114)
  line L7 (-45, 120) -> (37.35, 120)
  line L8 (-45, 0) -> (-45, 120)
  line L9 (36.6, 0) -> (-45, 0)
  line L10 (36.6, 22.25) -> (36.6, 0)
  line L11 (36.1, 22.75) -> (36.6, 22.25)
  line L12 (33, 22.75) -> (36.1, 22.75)
  line L13 (33, 96.75) -> (33, 22.75)
  line L14 (27, 96.75) -> (33, 96.75)
  line L15 (-9.25, 37) -> (-9.25, 20)
  line L16 (-0.75, 37) -> (-9.25, 37)
  line L17 (-0.75, 20) -> (-0.75, 37)
  line L18 (-9.25, 20) -> (-0.75, 20)
  line L19 (-8.2, 63) -> (-8.2, 65.1716)
  line L20 (-5.5, 63) -> (-8.2, 63)
  line L21 (-5.5, 46) -> (-5.5, 63)
  line L22 (-8.2, 46) -> (-5.5, 46)
  line L23 (-8.2, 41.8284) -> (-8.2, 46)
  curve K1 (-8.2, 41.8284) -> (-11.0284, 39)
  line L24 (-20, 39) -> (-11.0284, 39)
  line L25 (-11.0284, 68) -> (-20, 68)
  curve K2 (-11.0284, 68) -> (-8.2, 65.1716)
  circle C1 centre (29, 12) radius 1.65
  circle C2 centre (25, 108) radius 1.65
  circle C3 centre (-40.5, 54) radius 1.65
  arc A1 centre (-20, 53.5) radius 14.5 clockwise from (-20, 39) to (-20, 68)
sketch "Sketch18" plane through (3.825, 5, 60) normal (0, 1, 0) x axis (-1, 0, 0)
  line L1 (5.5477, 25) -> (5.5477, 60)
  line L2 (28.825, 25) -> (5.5477, 25)
  line L3 (28.825, 55.7156) -> (28.825, 25)
  line L4 (21.6767, 55.7156) -> (28.825, 55.7156)
  curve K1 (21.6767, 55.7156) -> (16.7623, 60)
  line L5 (5.5477, 60) -> (16.7623, 60)
  line L6 (5.5477, -25) -> (5.5477, 10)
  line L7 (16.7623, -25) -> (5.5477, -25)
  curve K2 (16.7623, -25) -> (21.6767, -20.7156)
  line L8 (28.825, -20.7156) -> (21.6767, -20.7156)
  line L9 (28.825, 10) -> (28.825, -20.7156)
  line L10 (5.5477, 10) -> (28.825, 10)
  line L11 (-16.2063, 60) -> (-16.2063, 25)
  line L12 (-28.3185, 60) -> (-16.2063, 60)
  curve K3 (-28.3185, 60) -> (-33.233, 55.7156)
  line L13 (-41.175, 55.7156) -> (-33.233, 55.7156)
  line L14 (-41.175, 25) -> (-41.175, 55.7156)
  line L15 (-16.2063, 25) -> (-41.175, 25)
  line L16 (-16.2063, 10) -> (-16.2063, 8)
  line L17 (-41.175, 10) -> (-16.2063, 10)
  line L18 (-41.175, -20.716) -> (-41.175, 10)
  line L19 (-33.233, -20.716) -> (-41.175, -20.716)
  line L20 (-33.233, -20.7156) -> (-33.233, -20.716)
  curve K4 (-33.233, -20.7156) -> (-28.3185, -25)
  line L21 (-16.2063, -25) -> (-28.3185, -25)
  line L22 (-16.2063, -21) -> (-16.2063, -25)
  line L23 (-5.7781, 46.248) -> (-5.7781, 60)
  line L24 (-31.2319, -43.4289) -> (-31.2319, 60)
  line L25 (21.7528, 45.1858) -> (17.7894, 47.5574)
  line L26 (25.7884, 47.4324) -> (21.7528, 45.1858)
  line L27 (25.8606, 52.0506) -> (25.7884, 47.4324)
  line L28 (21.8972, 54.4223) -> (25.8606, 52.0506)
  line L29 (17.8616, 52.1757) -> (21.8972, 54.4223)
  line L30 (17.7894, 47.5574) -> (17.8616, 52.1757)
  line L31 (25.825, 29.3676) -> (21.825, 27.0582)
  line L32 (25.825, 33.9864) -> (25.825, 29.3676)
  line L33 (21.825, 36.2958) -> (25.825, 33.9864)
  line L34 (17.825, 33.9864) -> (21.825, 36.2958)
  line L35 (17.825, 29.3676) -> (17.825, 33.9864)
  line L36 (21.825, 27.0582) -> (17.825, 29.3676)
  line L37 (-29.3456, 47.5574) -> (-29.4178, 52.1757)
  line L38 (-29.4178, 52.1757) -> (-33.4534, 54.4223)
  line L39 (-33.4534, 54.4223) -> (-37.4168, 52.0506)
  line L40 (-37.4168, 52.0506) -> (-37.3447, 47.4324)
  line L41 (-37.3447, 47.4324) -> (-33.309, 45.1858)
  line L42 (-33.309, 45.1858) -> (-29.3456, 47.5574)
  line L43 (-29.3812, 33.9864) -> (-33.3812, 36.2958)
  line L44 (-33.3812, 36.2958) -> (-37.3812, 33.9864)
  line L45 (-37.3812, 33.9864) -> (-37.3812, 29.3676)
  line L46 (-37.3812, 29.3676) -> (-33.3812, 27.0582)
  line L47 (-33.3812, 27.0582) -> (-29.3812, 29.3676)
  line L48 (-29.3812, 29.3676) -> (-29.3812, 33.9864)
  line L49 (21.825, 31.677) -> (21.825, 49.804)
  arc A1 centre (-16.175, -6.5) radius 14.5 clockwise from (-16.2063, -21) to (-16.2063, 8)
  circle C1 centre (21.825, 31.677) radius 2.5
  circle C2 centre (21.825, 49.804) radius 2.5
  circle C3 centre (-33.3812, 31.677) radius 2.5
  circle C4 centre (-33.3812, 49.804) radius 2.5
  point P32 (-5.7781, 60)
  point P33 (-5.7781, 60)
  point P38 (21.825, 49.804)
  point P47 (21.825, 49.804)
  point P37 (21.825, 31.677)
  point P54 (21.825, 31.677)
  point P41 (17.7894, 47.5574)
  point P56 (-29.3456, 47.5574)
  point P42 (21.7528, 45.1858)
  point P60 (-33.309, 45.1858)
  point P43 (25.7884, 47.4324)
  point P59 (-37.3447, 47.4324)
  point P44 (25.8606, 52.0506)
  point P58 (-37.4168, 52.0506)
  point P45 (21.8972, 54.4223)
  point P57 (-33.4534, 54.4223)
  point P46 (17.8616, 52.1757)
  point P55 (-29.4178, 52.1757)
  point P48 (21.825, 27.0582)
  point P65 (-33.3812, 27.0582)
  point P49 (25.825, 29.3676)
  point P64 (-37.3812, 29.3676)
  point P50 (25.825, 33.9864)
  point P63 (-37.3812, 33.9864)
  point P51 (21.825, 36.2958)
  point P61 (-33.3812, 36.2958)
  point P52 (17.825, 33.9864)
  point P62 (-29.3812, 33.9864)
  point P53 (17.825, 29.3676)
  point P66 (-29.3812, 29.3676)
  point P67 (21.825, 49.804)
  point P68 (21.825, 31.677)
  coincident P32 P33
  vertical L23
  symmetric L23 C1 C3
  symmetric L23 C2 C4
  coincident P38 P47
  coincident P37 P54
  vertical L35
  symmetric L23 P41 P56
  symmetric L23 P42 P60
  symmetric L23 P43 P59
  symmetric L23 P44 P58
  symmetric L23 P45 P57
  symmetric L23 P46 P55
  symmetric L23 P48 P65
  symmetric L23 P49 P64
  symmetric L23 P50 P63
  symmetric L23 P51 P61
  symmetric L23 P52 P62
  symmetric L23 P53 P66
  coincident P47 P67
  coincident P37 P68
  vertical L49
  dimension "d45" diameter C1 = 5
  dimension "d46" diameter C2 = 5
  dimension "d51" distance P47 L30 = 4
  dimension "d52" distance P54 L36 = 4
  dimension "d60" distance L3 L49 = 7
extrude "Extrude17" cut sketch "Sketch18" profile of L24 C1 C2 C3 C4 against normal blind 33
chamfer "Chamfer2" distance 2.35 (= "( ( 9.7 - 5 ) / 2 ) * 1 mm") Rotate Angle 45 bodies "Body1 (1)"
extrude "Extrude18" cut sketch "Sketch18" profile of L24 C1 C2 C3 C4 L25 L26 L27 L28 L29 L30 L31 L32 L33 L34 L35 L36 L37 L38 L39 L40 L41 L42 L43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 against normal blind 30 and against normal blind 12
copy_paste_bodies "CopyPasteBodies2"
mirror "Mirror1" mirrorStitchTolerance 0.1
move "Move6"
extrude "Extrude19" add of existing geometry blind 2.7
sketch "Sketch19" plane through (0, -36.8764, 0) normal (0, -1, 0) x axis (1, 0, 0)
  line L1 (49.05, 120) -> (52.0502, 115.7156)
  line L2 (42.0493, 120) -> (49.05, 120)
  line L3 (42.0493, 85) -> (42.0493, 120)
  line L4 (52.0502, 85) -> (42.0493, 85)
  line L5 (52.0502, 115.7156) -> (52.0502, 85)
  line L6 (63.8816, 85) -> (52.0502, 85)
  line L7 (62.8633, 100.274) -> (52.0502, 115.7156)
  line L8 (62.8633, 85) -> (62.8633, 100.274)
  line L9 (57.4567, 85) -> (57.4567, 107.9948)
  line L10 (49.6996, 92.2503) -> (49.6996, 105.2503)
  circle C1 centre (49.6996, 92.2503) radius 2.5
  circle C2 centre (49.6996, 92.2503) radius 4.25
  circle C3 centre (49.6996, 105.2503) radius 4.25
  circle C4 centre (49.6996, 105.2503) radius 2.5
  point P6 (52.0502, 85)
  point P7 (52.0502, 85)
  point P2 (52.0502, 115.7156)
  point P9 (52.0502, 115.7156)
  point P11 (62.8633, 85)
  point P16 (57.4567, 107.9948)
  point P17 (57.4567, 85)
  point P14 (49.6996, 105.2503)
  point P18 (49.6996, 105.2503)
  point P12 (49.6996, 92.2503)
  point P19 (49.6996, 92.2503)
  coincident P6 P7
  perpendicular L5 L6
  coincident P2 P9
  parallel L1 L7
  coincident L6 P11
  perpendicular L6 L8
  concentric C1 C2
  concentric C3 C4
  midpoint L7 P16
  coincident L6 P17
  perpendicular L6 L9
  coincident P14 P18
  coincident P12 P19
  parallel L5 L10
  dimension "d63" diameter C1 = 5
  dimension "d64" diameter C2 = 8.5
  dimension "d65" diameter C4 = 5
  dimension "d66" diameter C3 = 8.5
extrude "Extrude20" add sketch "Sketch19" profile of L1 L2 L3 L4 L5 L6 L7 C1 C2 C3 C4 L9 against normal blind 10
sketch "Sketch20" plane through (0, -37.8764, 0) normal (0, 1, 0) x axis (-1, 0, 0)
  line L1 (-52.0502, 115.7156) -> (-49.05, 120)
  line L2 (-52.0502, 85) -> (-52.0502, 115.7156)
  line L3 (-42.0493, 85) -> (-52.0502, 85)
  line L4 (-42.0493, 120) -> (-42.0493, 85)
  line L5 (-49.05, 120) -> (-42.0493, 120)
  line L6 (-49.05, 120) -> (-57.4567, 107.9948)
  line L7 (-42.0493, 120) -> (-49.05, 120)
  line L8 (-42.0493, 85) -> (-42.0493, 120)
  line L9 (-57.4567, 85) -> (-42.0493, 85)
  line L10 (-57.4567, 107.9948) -> (-57.4567, 85)
extrude "Extrude21" add sketch "Sketch20" against normal blind 10
chamfer "Chamfer3" distance 3 Rotate Angle 45 bodies "Body1 (1)"
fillet "Fillet1" radius 2 bodies "Body1 (1)"
fillet "Fillet2" radius 3.5 bodies "Body1 (1)"
fillet "Fillet3" radius 1 bodies "Body1 (1)"
extrude "Extrude22" cut sketch "Sketch19" profile of L5 C1 C4 along normal blind 27 and against normal blind 22
extrude "Extrude23" cut sketch "Sketch19" profile of L5 C1 C2 C3 C4 L10 along normal blind 26 and along normal blind 7
sketch "Sketch21" plane through (0, -36.8764, 0) normal (0, -1, 0) x axis (1, 0, 0)
  line L1 (43.0195, 85) -> (43.0195, 120)
  line L2 (54.4567, 85) -> (43.0195, 85)
  line L3 (56.4316, 86.9749) -> (54.4567, 85)
  line L4 (57.4567, 106.8912) -> (57.4567, 89.4497)
  line L5 (49.05, 120) -> (56.8237, 108.8988)
  line L6 (43.0195, 120) -> (49.05, 120)
  line L7 (49.6996, 100.6315) -> (45.6996, 102.9409)
  line L8 (53.6996, 102.9409) -> (49.6996, 100.6315)
  line L9 (53.6996, 107.5597) -> (53.6996, 102.9409)
  line L10 (49.6996, 109.8691) -> (53.6996, 107.5597)
  line L11 (45.6996, 107.5597) -> (49.6996, 109.8691)
  line L12 (45.6996, 102.9409) -> (45.6996, 107.5597)
  line L13 (49.6996, 87.6315) -> (45.6996, 89.9409)
  line L14 (53.6996, 89.9409) -> (49.6996, 87.6315)
  line L15 (53.6996, 94.5597) -> (53.6996, 89.9409)
  line L16 (49.6996, 96.8691) -> (53.6996, 94.5597)
  line L17 (45.6996, 94.5597) -> (49.6996, 96.8691)
  line L18 (45.6996, 89.9409) -> (45.6996, 94.5597)
  circle C1 centre (49.6996, 105.2503) radius 2.5
  circle C2 centre (49.6996, 92.2503) radius 2.5
  arc A1 centre (53.9567, 89.4497) radius 3.5 clockwise from (57.4567, 89.4497) to (56.4316, 86.9749)
  arc A2 centre (53.9567, 106.8912) radius 3.5 clockwise from (56.8237, 108.8988) to (57.4567, 106.8912)
  point P2 (49.6996, 105.2503)
  point P20 (49.6996, 105.2503)
  point P3 (49.6996, 92.2503)
  point P27 (49.6996, 92.2503)
  coincident P2 P20
  coincident P3 P27
  dimension "d87" distance P20 L12 = 4
  dimension "d88" distance P27 L18 = 4
extrude "Extrude24" cut sketch "Sketch21" profile of C1 C2 L7 L8 L9 L10 L11 L12 L13 L14 L15 L16 L17 L18 against normal blind 24 and against normal blind 5
offset_faces "OffsetFaces1" distance -0.2
sketch "Sketch22" plane through (0, 0, 120) normal (0, 0, 1) x axis (-1, 0, 0)
  line L1 (28.4052, 37.6156) -> (22.7882, 39.3271)
  line L2 (22.7882, 35.4258) -> (28.4052, 37.1373)
  line L3 (1.7227, 5) -> (1.7227, 6.9671)
  line L4 (12.9373, 5) -> (1.7227, 5)
  line L5 (-49.05, 37.8764) -> (-49.05, 45.8764)
  line L6 (-43.0195, 37.8764) -> (-49.05, 37.8764)
  line L7 (-49.05, 36.8764) -> (-49.05, 37.8764)
  line L8 (-49.05, 37.3764) -> (-49.05, 36.8764)
  line L9 (-49.05, 37.3764) -> (-39.5803, 37.3764)
  line L10 (-61.1821, 37.3764) -> (-39.5803, 37.3764)
  line L11 (-61.1821, 36.3764) -> (-61.1821, 37.3764)
  line L12 (-39.5803, 36.3764) -> (-61.1821, 36.3764)
  line L13 (-39.5803, 37.3764) -> (-39.5803, 36.3764)
  line L14 (-61.1821, 38.3764) -> (-61.1821, 37.3764)
  line L15 (-39.5803, 38.3764) -> (-61.1821, 38.3764)
  line L16 (-39.5803, 37.3764) -> (-39.5803, 38.3764)
  arc A1 centre (-43.0195, 38.8764) radius 1 clockwise from (-42.0205, 38.8316) to (-43.0195, 37.8764)
  arc A2 centre (-9.6031, 37.3764) radius 32.45 clockwise from (-42.0205, 38.8316) to (22.7882, 39.3271)
  arc A3 centre (28.3324, 37.3764) radius 0.25 clockwise from (28.4052, 37.6156) to (28.4052, 37.1373)
  arc A4 centre (-9.6031, 37.3764) radius 32.45 clockwise from (22.7882, 35.4258) to (1.7227, 6.9671)
  arc A5 centre (-9.6031, 37.3764) radius 39.45 clockwise from (-47.6862, 47.671) to (12.9373, 5)
  closed curve K1 centre (-46.6083, 45.8764)
  point P17 (-49.05, 37.8764)
  point P20 (-49.05, 37.8764)
  point P19 (-49.05, 36.8764)
  point P21 (-49.05, 36.8764)
  point P22 (-49.05, 37.3764)
  point P23 (-39.5803, 37.3764)
  point P30 (-39.5803, 37.3764)
  point P24 (-61.1821, 37.3764)
  point P27 (-61.1821, 37.3764)
  point P25 (-61.1821, 36.3764)
  point P28 (-61.1821, 38.3764)
  point P26 (-39.5803, 36.3764)
  point P29 (-39.5803, 38.3764)
  coincident P17 P20
  coincident P19 P21
  midpoint L7 P22
  perpendicular L8 L9
  horizontal L10
  vertical L11
  horizontal L12
  vertical L13
  symmetric P23 L10 P30
  symmetric P24 L10 P27
  symmetric P25 L10 P28
  symmetric P26 L10 P29
  dimension "d94" distance P23 P26 = 1
extrude "Extrude25" cut sketch "Sketch22" profile of A1 L5 L6 L7 L9 L10 L11 L12 L13 L14 L15 L16 against normal blind 60
mirror "Mirror2" mirrorStitchTolerance 0.1
move "Move7"
sketch "Sketch23" plane through (0, 5, 0) normal (0, 1, 0) x axis (-1, 0, 0)
  line L1 (27, 97.25) -> (27, 96.75)
  line L2 (33.7929, 97.25) -> (27, 97.25)
  line L3 (35, 98.4571) -> (33.7929, 97.25)
  line L4 (35, 114) -> (35, 98.4571)
  line L5 (37.35, 114) -> (35, 114)
  line L6 (37.35, 120) -> (37.35, 114)
  line L7 (-45, 120) -> (37.35, 120)
  line L8 (-45, 0) -> (-45, 120)
  line L9 (36.6, 0) -> (-45, 0)
  line L10 (36.6, 22.25) -> (36.6, 0)
  line L11 (36.1, 22.75) -> (36.6, 22.25)
  line L12 (33, 22.75) -> (36.1, 22.75)
  line L13 (33, 96.75) -> (33, 22.75)
  line L14 (27, 96.75) -> (33, 96.75)
  line L15 (-9.25, 37) -> (-9.25, 20)
  line L16 (-0.75, 37) -> (-9.25, 37)
  line L17 (-0.75, 20) -> (-0.75, 37)
  line L18 (-9.25, 20) -> (-0.75, 20)
  line L19 (-8.2, 63) -> (-8.2, 65.1716)
  line L20 (-5.5, 63) -> (-8.2, 63)
  line L21 (-5.5, 46) -> (-5.5, 63)
  line L22 (-8.2, 46) -> (-5.5, 46)
  line L23 (-8.2, 41.8284) -> (-8.2, 46)
  curve K1 (-8.2, 41.8284) -> (-11.0284, 39)
  line L24 (-20, 39) -> (-11.0284, 39)
  line L25 (-11.0284, 68) -> (-20, 68)
  curve K2 (-11.0284, 68) -> (-8.2, 65.1716)
  circle C1 centre (18, 109.804) radius 4.85
  circle C2 centre (-37.2062, 109.804) radius 4.85
  circle C3 centre (29, 12) radius 1.65
  circle C4 centre (25, 108) radius 1.65
  circle C5 centre (-40.5, 54) radius 1.65
  arc A1 centre (-20, 53.5) radius 14.5 clockwise from (-20, 39) to (-20, 68)
  circle C6 centre (-37.2062, 91.677) radius 4.85
  circle C7 centre (18, 91.677) radius 4.85
  circle C8 centre (18, 45.196) radius 2.5
  circle C9 centre (18, 45.196) radius 2.5
  circle C10 centre (18, 63.323) radius 2.5
  circle C11 centre (18, 63.323) radius 2.5
extrude "Extrude26" cut sketch "Sketch23" profile of C8 C9 C10 C11 against normal blind 35
chamfer "Chamfer4" distance 2.35 (= "( ( 9.7 - 5 ) / 2 ) * 1 mm") Rotate Angle 45 bodies "Body1 (1)"
fillet "Fillet4" radius 2.25 bodies "Body1 (1)"
sketch "Sketch24" plane through (0, -9.7, 0) normal (0, -1, 0) x axis (1, 0, 0)
  line L1 (37.2062, 58.7042) -> (33.2062, 61.0136)
  line L2 (41.2062, 61.0136) -> (37.2062, 58.7042)
  line L3 (41.2062, 65.6324) -> (41.2062, 61.0136)
  line L4 (37.2062, 67.9418) -> (41.2062, 65.6324)
  line L5 (33.2062, 65.6324) -> (37.2062, 67.9418)
  line L6 (33.2062, 61.0136) -> (33.2062, 65.6324)
  line L7 (33.2428, 42.8243) -> (33.1706, 47.4426)
  line L8 (37.2784, 40.5777) -> (33.2428, 42.8243)
  line L9 (41.2418, 42.9494) -> (37.2784, 40.5777)
  line L10 (41.1697, 47.5676) -> (41.2418, 42.9494)
  line L11 (37.134, 49.8142) -> (41.1697, 47.5676)
  line L12 (33.1706, 47.4426) -> (37.134, 49.8142)
  circle C1 centre (37.2062, 63.323) radius 2.5
  circle C2 centre (37.2062, 45.196) radius 2.5
extrude "Extrude27" new body sketch "Sketch24" along normal blind 21
split "Split6"
combine "Combine5"
split "Split7"
sketch "Sketch25" plane through (0, 5, 0) normal (0, 1, 0) x axis (-1, 0, 0)
  line L1 (27, 97.25) -> (27, 96.75)
  line L2 (33.7929, 97.25) -> (27, 97.25)
  line L3 (35, 98.4571) -> (33.7929, 97.25)
  line L4 (35, 114) -> (35, 98.4571)
  line L5 (37.35, 114) -> (35, 114)
  line L6 (37.35, 120) -> (37.35, 114)
  line L7 (-45, 120) -> (37.35, 120)
  line L8 (-45, 0) -> (-45, 120)
  line L9 (36.6, 0) -> (-45, 0)
  line L10 (36.6, 22.25) -> (36.6, 0)
  line L11 (36.1, 22.75) -> (36.6, 22.25)
  line L12 (33, 22.75) -> (36.1, 22.75)
  line L13 (33, 96.75) -> (33, 22.75)
  line L14 (27, 96.75) -> (33, 96.75)
  line L15 (-9.25, 37) -> (-9.25, 20)
  line L16 (-0.75, 37) -> (-9.25, 37)
  line L17 (-0.75, 20) -> (-0.75, 37)
  line L18 (-9.25, 20) -> (-0.75, 20)
  line L19 (-8.2, 63) -> (-8.2, 65.1716)
  line L20 (-5.5, 63) -> (-8.2, 63)
  line L21 (-5.5, 46) -> (-5.5, 63)
  line L22 (-8.2, 46) -> (-5.5, 46)
  line L23 (-8.2, 41.8284) -> (-8.2, 46)
  curve K1 (-8.2, 41.8284) -> (-11.0284, 39)
  line L24 (-20, 39) -> (-11.0284, 39)
  line L25 (-11.0284, 68) -> (-20, 68)
  curve K2 (-11.0284, 68) -> (-8.2, 65.1716)
  circle C1 centre (18, 63.323) radius 4.85
  circle C2 centre (18, 109.804) radius 4.85
  circle C3 centre (-37.2062, 109.804) radius 4.85
  circle C4 centre (29, 12) radius 1.65
  circle C5 centre (25, 108) radius 1.65
  circle C6 centre (-40.5, 54) radius 1.65
  arc A1 centre (-20, 53.5) radius 14.5 clockwise from (-20, 39) to (-20, 68)
  circle C7 centre (-37.2062, 91.677) radius 4.85
  circle C8 centre (18, 91.677) radius 4.85
  circle C9 centre (18, 45.196) radius 4.85
extrude "Extrude28" add of existing geometry to an object
sketch "Sketch26" plane through (0, -5, 0) normal (0, 1, 0) x axis (-1, 0, 0)
  line L1 (-20.0313, 70) -> (-20.0313, 68)
  line L2 (-45, 70) -> (-20.0313, 70)
  line L3 (-45, 39.2844) -> (-45, 70)
  line L4 (-37.058, 39.2844) -> (-45, 39.2844)
  curve K1 (-32.1435, 35) -> (-37.058, 39.2844)
  line L5 (-20.0313, 35) -> (-32.1435, 35)
  line L6 (-20.0313, 39) -> (-20.0313, 35)
  arc A1 centre (-20, 53.5) radius 14.5 clockwise from (-20.0313, 39) to (-20.0313, 68)
  circle C1 centre (-38.5716, 64.0954) radius 2.5
  circle C2 centre (-39.2174, 45.1209) radius 2.5
  dimension "d110" diameter C1 = 5
  dimension "d111" diameter C2 = 5
extrude "Extrude29" cut sketch "Sketch26" profile of C1 C2 along normal blind 40 and against normal blind 30
chamfer "Chamfer5" distance 2.35 (= "( ( 9.7 - 5 ) / 2 ) * 1 mm") Rotate Angle 45 bodies "Body1 (1)"
extrude "Extrude30" new body of existing geometry blind 3
combine "Combine6"
sketch "Sketch27" plane through (0, -5, 0) normal (0, -1, 0) x axis (1, 0, 0)
  line L1 (9.25, 37) -> (0.75, 37)
  line L2 (9.25, 20) -> (9.25, 37)
  line L3 (0.75, 20) -> (9.25, 20)
  line L4 (0.75, 37) -> (0.75, 20)
  line L5 (11.8531, 68) -> (11.8531, 91.3543)
  line L6 (20, 68) -> (11.8531, 68)
  line L7 (11.0284, 39) -> (20, 39)
  curve K1 (11.0284, 39) -> (8.2, 41.8284)
  line L8 (8.2, 46) -> (8.2, 41.8284)
  line L9 (2.2, 46) -> (8.2, 46)
  line L10 (2.2, 63) -> (2.2, 46)
  line L11 (7.3531, 63) -> (2.2, 63)
  line L12 (7.3531, 91.3543) -> (7.3531, 63)
  line L13 (11.8531, 91.3543) -> (7.3531, 91.3543)
  line L14 (48, 0) -> (-35.5, 0)
  line L15 (48, 120) -> (48, 0)
  line L16 (-34.35, 120) -> (48, 120)
  line L17 (-34.35, 114) -> (-34.35, 120)
  line L18 (-30.35, 114) -> (-34.35, 114)
  line L19 (-30.35, 96.75) -> (-30.35, 114)
  line L20 (-33, 96.75) -> (-30.35, 96.75)
  line L21 (-33, 23.25) -> (-33, 96.75)
  line L22 (-35.5, 23.25) -> (-33, 23.25)
  line L23 (-35.5, 15.3775) -> (-35.5, 23.25)
  line L24 (-31.6, 12) -> (-35.5, 15.3775)
  line L25 (-35.5, 8.6225) -> (-31.6, 12)
  line L26 (-35.5, 0) -> (-35.5, 8.6225)
  line L27 (38.5716, 68.7142) -> (42.5716, 66.4048)
  line L28 (34.5716, 66.4048) -> (38.5716, 68.7142)
  line L29 (34.5716, 61.786) -> (34.5716, 66.4048)
  line L30 (38.5716, 59.4766) -> (34.5716, 61.786)
  line L31 (42.5716, 61.786) -> (38.5716, 59.4766)
  line L32 (42.5716, 66.4048) -> (42.5716, 61.786)
  line L33 (39.2174, 49.7397) -> (43.2174, 47.4303)
  line L34 (35.2174, 47.4303) -> (39.2174, 49.7397)
  line L35 (35.2174, 42.8115) -> (35.2174, 47.4303)
  line L36 (39.2174, 40.5021) -> (35.2174, 42.8115)
  line L37 (43.2174, 42.8115) -> (39.2174, 40.5021)
  line L38 (43.2174, 47.4303) -> (43.2174, 42.8115)
  circle C1 centre (-29, 12) radius 1.65
  circle C2 centre (40.5, 54) radius 1.65
  circle C3 centre (-25, 108) radius 1.65
  arc A1 centre (20, 53.5) radius 14.5 clockwise from (20, 68) to (20, 39)
  circle C4 centre (37.2062, 91.677) radius 2.5
  circle C5 centre (-18, 109.804) radius 2.5
  circle C6 centre (37.2062, 109.804) radius 2.5
  circle C7 centre (-18, 91.677) radius 2.5
  circle C8 centre (-18, 45.196) radius 2.5
  circle C9 centre (-18, 63.323) radius 2.5
  circle C10 centre (39.2174, 45.1209) radius 2.5
  circle C11 centre (38.5716, 64.0954) radius 2.5
  circle C12 centre (38.5716, 64.0954) radius 2.5
  circle C13 centre (39.2174, 45.1209) radius 2.5
  point P28 (38.5716, 64.0954)
  point P50 (38.5716, 64.0954)
  point P27 (39.2174, 45.1209)
  point P57 (39.2174, 45.1209)
  coincident P28 P50
  vertical L32
  coincident P27 P57
  vertical L38
  dimension "d120" distance P50 L32 = 4
  dimension "d121" distance P57 L38 = 4
sketch "Sketch28" plane through (45, 0, 0) normal (1, 0, 0) x axis (0, 1, 0)
  line L1 (-5, 70) -> (-5, 39.2844)
  line L2 (-13.9443, 70) -> (-5, 70)
  line L3 (-13.9443, 39.2844) -> (-13.9443, 70)
  line L4 (-5, 39.2844) -> (-13.9443, 39.2844)
extrude "Extrude31" cut sketch "Sketch27" profile of C10 C11 C12 C13 L27 L28 L29 L30 L31 L32 L33 L34 L35 L36 L37 L38 along normal blind 26 and along normal blind 5
copy_paste_bodies "CopyPasteBodies3"
move "Move8"
work_plane "WorkPlane3" AlongDistance 0
sketch "Sketch29" plane through (149.6031, -5.561, 91.3543) normal (0, 0, 1) x axis (1, 0, 0)
  line L1 (38.3969, 0.561) -> (-43.9531, 0.561)
  line L2 (38.3969, 10.561) -> (38.3969, 0.561)
  line L3 (-46.9531, 10.561) -> (38.3969, 10.561)
  line L4 (-46.9531, 3.561) -> (-46.9531, 10.561)
  line L5 (-43.9531, 0.561) -> (-46.9531, 3.561)
  line L6 (0, -10.1748) -> (0, 0)
  line L7 (-8.2343, -6.6632) -> (0, 0)
  line L8 (-13.2343, -6.6632) -> (-8.2343, -6.6632)
  line L9 (-13.2343, 0.561) -> (-13.2343, -6.6632)
  line L10 (13.2343, 0.561) -> (13.2343, -6.6632)
  line L11 (13.2343, -6.6632) -> (8.2343, -6.6632)
  line L12 (8.2343, -6.6632) -> (0, 0)
  circle C1 centre (-42.9531, 5.561) radius 2.625
  point P1 (0, 0)
  point P8 (0, 0)
  point P12 (-13.2343, 0.561)
  point P16 (0, 0)
  point P10 (-8.2343, -6.6632)
  point P13 (8.2343, -6.6632)
  point P11 (-13.2343, -6.6632)
  point P14 (13.2343, -6.6632)
  point P15 (13.2343, 0.561)
  coincident P1 P8
  perpendicular L1 L6
  perpendicular L6 L8
  coincident L1 P12
  perpendicular L1 L9
  symmetric P8 L6 P16
  symmetric L6 P10 P13
  symmetric L6 P11 P14
  symmetric L6 P12 P15
  dimension "d128" distance P10 P11 = 5
extrude "Extrude32" add sketch "Sketch29" profile of L1 L7 L8 L9 L10 L11 L12 blind -5 Side2Offset 0
extrude "Extrude33" cut of existing geometry to an object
